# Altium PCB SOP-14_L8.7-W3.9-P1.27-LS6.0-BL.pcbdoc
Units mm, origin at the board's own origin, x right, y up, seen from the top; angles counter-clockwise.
Board outline 21.99 x 19.36 mm, 2 copper layers (Top Layer, Bottom Layer), stack 0 mm thick; 1 components, 0 nets, 14 pads, 0 vias.
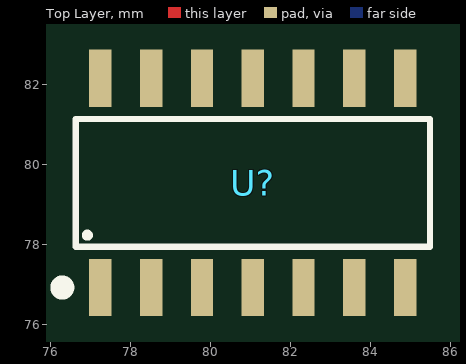
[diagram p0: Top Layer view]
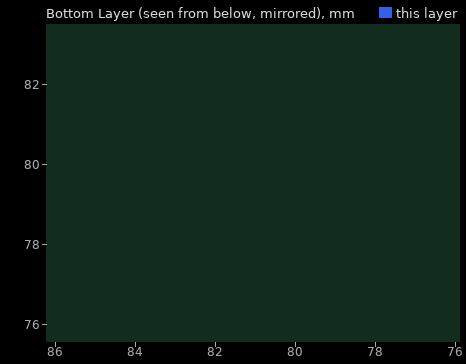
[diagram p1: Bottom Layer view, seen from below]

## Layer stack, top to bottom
Top Layer: signal copper (thickness not stored)
Bottom Layer: signal copper (thickness not stored)

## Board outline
91.839,69.85 69.85,69.85 69.85,89.21 91.839,89.21

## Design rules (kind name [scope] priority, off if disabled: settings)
PasteMaskExpansion "Paste Mask Expansion" [All] p1: expansion=0
SolderMaskExpansion "Solder Mask Expansion" [IsVia] p1: expansion=-25.4 istentingtop=TRUE
SolderMaskExpansion "Solder Mask Expansion" [All] p2: expansion=0.051 istentingtop=FALSE

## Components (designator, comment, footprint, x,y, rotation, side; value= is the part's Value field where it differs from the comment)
U? "" SOP-14_L8.7-W3.9-P1.27-LS6.0-BL 81.063,79.53 r0 top

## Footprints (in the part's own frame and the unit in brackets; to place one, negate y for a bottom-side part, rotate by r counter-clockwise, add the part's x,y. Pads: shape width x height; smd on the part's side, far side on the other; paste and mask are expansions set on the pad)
SOP-14_L8.7-W3.9-P1.27-LS6.0-BL [mm]
  rect 0.56x1.43 smd: 1(-3.81,-2.615) 2(-2.54,-2.615) 3(-1.27,-2.615) 4(0,-2.615) 5(1.27,-2.615) 6(2.54,-2.615) 7(3.81,-2.615) 8(3.81,2.615) 9(2.54,2.615) 10(1.27,2.615) 11(0,2.615) 12(-1.27,2.615) 13(-2.54,2.615) 14(-3.81,2.615)
  silkscreen extent -4.86,-2.71 4.43,1.6

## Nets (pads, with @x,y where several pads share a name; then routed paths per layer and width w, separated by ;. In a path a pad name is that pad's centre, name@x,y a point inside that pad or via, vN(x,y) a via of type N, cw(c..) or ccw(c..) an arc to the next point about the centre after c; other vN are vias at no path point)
pads on no net: U?.1 U?.2 U?.3 U?.4 U?.5 U?.6 U?.7 U?.8 U?.9 U?.10 U?.11 U?.12 U?.13 U?.14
